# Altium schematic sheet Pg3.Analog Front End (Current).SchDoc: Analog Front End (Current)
size 431 x 279 mm; Date: Not shown in title block; ApprovedBy: Not shown in title block; CheckedBy: Not shown in title block; Author: Not shown in title block; CompanyName: Not shown in title block; Engineer: Not shown in title block; Organization: Not shown in title block; Address1: Not shown in title block; Address2: Not shown in title block; Address3: Not shown in title block; Address4: Not shown in title block; DocumentNumber: 3; Revision: Use project parameter SCH_Rev; SheetNumber: 3; SheetTotal: 8; PageSetup: Record=PageOptions|CenterHorizontal=True|CenterVertical=True|PrintScale=1.00|XCorrection=1.00|YCorrection=1.00|PrintKind=0|BorderSize=5000000|LeftOffset=0|BottomOffset=0|Orientation=2|PaperLength=1000|PaperWidth=1000|Scale=100|PaperSource=15|PrintQuality=600|MediaType=1|DitherType=10|PaperKind=Letter|PrintScaleMode=1
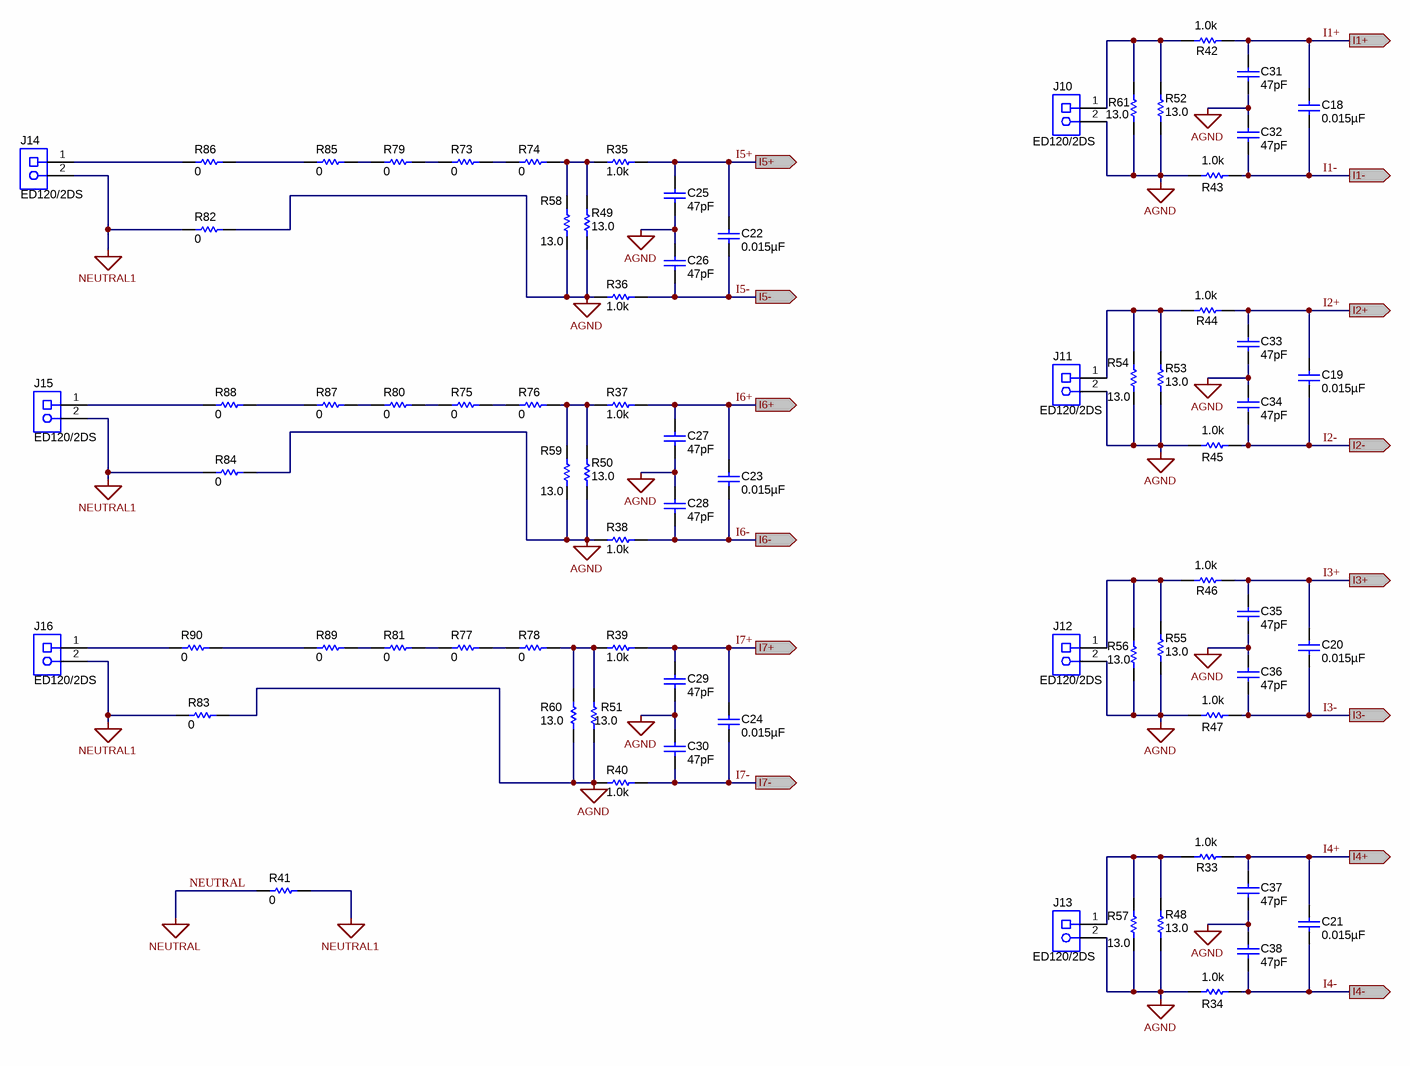
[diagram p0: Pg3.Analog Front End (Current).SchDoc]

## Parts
C18  ValueDisplayed: 0.015µF  [0805_HV]  (hidden comment: 08055C153KAT2A)
C19  ValueDisplayed: 0.015µF  [0805_HV]  (hidden comment: 08055C153KAT2A)
C20  ValueDisplayed: 0.015µF  [0805_HV]  (hidden comment: 08055C153KAT2A)
C21  ValueDisplayed: 0.015µF  [0805_HV]  (hidden comment: 08055C153KAT2A)
C22  ValueDisplayed: 0.015µF  [0805_HV]  (hidden comment: 08055C153KAT2A)
C23  ValueDisplayed: 0.015µF  [0805_HV]  (hidden comment: 08055C153KAT2A)
C24  ValueDisplayed: 0.015µF  [0805_HV]  (hidden comment: 08055C153KAT2A)
C25  ValueDisplayed: 47pF  [0805_HV]  (hidden comment: GRM21A5C2E470JW01D)
C26  ValueDisplayed: 47pF  [0805_HV]  (hidden comment: GRM21A5C2E470JW01D)
C27  ValueDisplayed: 47pF  [0805_HV]  (hidden comment: GRM21A5C2E470JW01D)
C28  ValueDisplayed: 47pF  [0805_HV]  (hidden comment: GRM21A5C2E470JW01D)
C29  ValueDisplayed: 47pF  [0805_HV]  (hidden comment: GRM21A5C2E470JW01D)
C30  ValueDisplayed: 47pF  [0805_HV]  (hidden comment: GRM21A5C2E470JW01D)
C31  ValueDisplayed: 47pF  [0805_HV]  (hidden comment: GRM21A5C2E470JW01D)
C32  ValueDisplayed: 47pF  [0805_HV]  (hidden comment: GRM21A5C2E470JW01D)
C33  ValueDisplayed: 47pF  [0805_HV]  (hidden comment: GRM21A5C2E470JW01D)
C34  ValueDisplayed: 47pF  [0805_HV]  (hidden comment: GRM21A5C2E470JW01D)
C35  ValueDisplayed: 47pF  [0805_HV]  (hidden comment: GRM21A5C2E470JW01D)
C36  ValueDisplayed: 47pF  [0805_HV]  (hidden comment: GRM21A5C2E470JW01D)
C37  ValueDisplayed: 47pF  [0805_HV]  (hidden comment: GRM21A5C2E470JW01D)
C38  ValueDisplayed: 47pF  [0805_HV]  (hidden comment: GRM21A5C2E470JW01D)
J10  ED120/2DS  [CONN_ED120-2DS]
J11  ED120/2DS  [CONN_ED120-2DS]
J12  ED120/2DS  [CONN_ED120-2DS]
J13  ED120/2DS  [CONN_ED120-2DS]
J14  ED120/2DS  [CONN_ED120-2DS]
J15  ED120/2DS  [CONN_ED120-2DS]
J16  ED120/2DS  [CONN_ED120-2DS]
R33  value 1.0k  [0603]  (hidden comment: CRCW06031K00JNEA)
R34  value 1.0k  [0603]  (hidden comment: CRCW06031K00JNEA)
R35  value 1.0k  [0603]  (hidden comment: CRCW06031K00JNEA)
R36  value 1.0k  [0603]  (hidden comment: CRCW06031K00JNEA)
R37  value 1.0k  [0603]  (hidden comment: CRCW06031K00JNEA)
R38  value 1.0k  [0603]  (hidden comment: CRCW06031K00JNEA)
R39  value 1.0k  [0603]  (hidden comment: CRCW06031K00JNEA)
R40  value 1.0k  [0603]  (hidden comment: CRCW06031K00JNEA)
R41  value 0  [0805_HV]  (hidden comment: CRCW08050000Z0EA)
R42  value 1.0k  [0603]  (hidden comment: CRCW06031K00JNEA)
R43  value 1.0k  [0603]  (hidden comment: CRCW06031K00JNEA)
R44  value 1.0k  [0603]  (hidden comment: CRCW06031K00JNEA)
R45  value 1.0k  [0603]  (hidden comment: CRCW06031K00JNEA)
R46  value 1.0k  [0603]  (hidden comment: CRCW06031K00JNEA)
R47  value 1.0k  [0603]  (hidden comment: CRCW06031K00JNEA)
R48  value 13.0  [0805_HV]  (hidden comment: CRCW080513R0FKEA)
R49  value 13.0  [0805_HV]  (hidden comment: CRCW080513R0FKEA)
R50  value 13.0  [0805_HV]  (hidden comment: CRCW080513R0FKEA)
R51  value 13.0  [0805_HV]  (hidden comment: CRCW080513R0FKEA)
R52  value 13.0  [0805_HV]  (hidden comment: CRCW080513R0FKEA)
R53  value 13.0  [0805_HV]  (hidden comment: CRCW080513R0FKEA)
R54  value 13.0  [0805_HV]  (hidden comment: CRCW080513R0FKEA)
R55  value 13.0  [0805_HV]  (hidden comment: CRCW080513R0FKEA)
R56  value 13.0  [0805_HV]  (hidden comment: CRCW080513R0FKEA)
R57  value 13.0  [0805_HV]  (hidden comment: CRCW080513R0FKEA)
R58  value 13.0  [0805_HV]  (hidden comment: CRCW080513R0FKEA)
R59  value 13.0  [0805_HV]  (hidden comment: CRCW080513R0FKEA)
R60  value 13.0  [0805_HV]  (hidden comment: CRCW080513R0FKEA)
R61  value 13.0  [0805_HV]  (hidden comment: CRCW080513R0FKEA)
R73  value 0  [0805_HV]  (hidden comment: CRCW08050000Z0EA)
R74  value 0  [0805_HV]  (hidden comment: CRCW08050000Z0EA)
R75  value 0  [0805_HV]  (hidden comment: CRCW08050000Z0EA)
R76  value 0  [0805_HV]  (hidden comment: CRCW08050000Z0EA)
R77  value 0  [0805_HV]  (hidden comment: CRCW08050000Z0EA)
R78  value 0  [0805_HV]  (hidden comment: CRCW08050000Z0EA)
R79  value 0  [0805_HV]  (hidden comment: CRCW08050000Z0EA)
R80  value 0  [0805_HV]  (hidden comment: CRCW08050000Z0EA)
R81  value 0  [0805_HV]  (hidden comment: CRCW08050000Z0EA)
R82  value 0  [0805_HV]  (hidden comment: CRCW08050000Z0EA)
R83  value 0  [0805_HV]  (hidden comment: CRCW08050000Z0EA)
R84  value 0  [0805_HV]  (hidden comment: CRCW08050000Z0EA)
R85  value 0  [0805_HV]  (hidden comment: CRCW08050000Z0EA)
R86  value 0  [0805_HV]  (hidden comment: CRCW08050000Z0EA)
R87  value 0  [0805_HV]  (hidden comment: CRCW08050000Z0EA)
R88  value 0  [0805_HV]  (hidden comment: CRCW08050000Z0EA)
R89  value 0  [0805_HV]  (hidden comment: CRCW08050000Z0EA)
R90  value 0  [0805_HV]  (hidden comment: CRCW08050000Z0EA)

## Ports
I1+ (out), I1- (out), I2+ (out), I2- (out), I3+ (out), I3- (out), I4+ (out), I4- (out), I5+ (out), I5- (out), I6+ (out), I6- (out), I7+ (out), I7- (out)

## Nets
AGND: C25.2 C26.1 C27.2 C28.1 C29.2 C30.1 C31.2 C32.1 C33.2 C34.1 C35.2 C36.1 C37.2 C38.1 J10.2 J11.2 J12.2 J13.2 R34.2 R36.2 R38.2 R40.2 R43.2 R45.2 R47.2 R48.1 R49.2 R50.2 R51.1 R52.1 R53.1 R54.1 R55.1 R56.1 R57.1 R58.1 R59.1 R60.2 R61.1 R82.2 R83.2 R84.2
NEUTRAL: R41.1
NEUTRAL1: J14.2 J15.2 J16.2 R41.2 R82.1 R83.1 R84.1
I1+: C18.1 C31.1 R42.1 ; port I1+
I1-: C18.2 C32.2 R43.1 ; port I1-
I2+: C19.1 C33.1 R44.1 ; port I2+
I2-: C19.2 C34.2 R45.1 ; port I2-
I3+: C20.1 C35.1 R46.1 ; port I3+
I3-: C20.2 C36.2 R47.1 ; port I3-
I4+: C21.1 C37.1 R33.1 ; port I4+
I4-: C21.2 C38.2 R34.1 ; port I4-
I5+: C22.1 C25.1 R35.1 ; port I5+
I5-: C22.2 C26.2 R36.1 ; port I5-
I6+: C23.1 C27.1 R37.1 ; port I6+
I6-: C23.2 C28.2 R38.1 ; port I6-
I7+: C24.1 C29.1 R39.1 ; port I7+
I7-: C24.2 C30.2 R40.1 ; port I7-
NetJ10_1: J10.1 R42.2 R52.2 R61.2
NetJ11_1: J11.1 R44.2 R53.2 R54.2
NetJ12_1: J12.1 R46.2 R55.2 R56.2
NetJ13_1: J13.1 R33.2 R48.2 R57.2
NetJ14_1: J14.1 R86.1
NetJ15_1: J15.1 R88.1
NetJ16_1: J16.1 R90.1
NetR35_2: R35.2 R49.1 R58.2 R74.2
NetR37_2: R37.2 R50.1 R59.2 R76.2
NetR39_2: R39.2 R51.2 R60.1 R78.2
NetR73_1: R73.1 R79.2
NetR73_2: R73.2 R74.1
NetR75_1: R75.1 R80.2
NetR75_2: R75.2 R76.1
NetR77_1: R77.1 R81.2
NetR77_2: R77.2 R78.1
NetR79_1: R79.1 R85.2
NetR80_1: R80.1 R87.2
NetR81_1: R81.1 R89.2
NetR85_1: R85.1 R86.2
NetR87_1: R87.1 R88.2
NetR89_1: R89.1 R90.2

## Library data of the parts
C18-C24 = 08055C153KAT2A: CAP, CERM, 0.015uF, 50V, +/-10%, X7R, 0805; Manufacturer: AVX; Polarized: N; CompType: Capacitor; U/M: EA; Cap_F: 0.000000015; Tolerance_%: 10; ESR_Ohm: 0.063; Value1: 0.063 ohm; VDC_V: 50; TaMin_C: -55; TaMax_C: 125; Cap_Case: 0805
C25-C38 = GRM21A5C2E470JW01D: CAP, CERM, 47pF, 500V, +/-5%, C0G/NP0, 0805; Manufacturer: MuRata; Polarized: N; CompType: Capacitor; U/M: EA; Cap_F: 0.000000000047; Tolerance_%: 5; Value1: Unknown; VDC_V: 250; Value2: 250V; TaMin_C: -55; TaMax_C: 125; Cap_Case: 0805
J10-J16 = ED120/2DS: TERMINAL BLOCK 5.08MM VERT 2POS, TH; Manufacturer: On-Shore Technology; SymbolCreator: a0412235; U/M: EA
R33-R40 R42-R47 = RC0603JR-071KL: RES, 1.0k ohm, 5%, 0.1W, 0603; Manufacturer: Vishay-Dale; CompType: Resistor; Res_ohm: 1000; Value_Code: 1k00; Tolerance_%: 5; Power_W: 0.1; VDC_V: 50; TempCo: 100 ppm/C; EIA_Code: E24; U/M: EA
R41 R73-R90 = CRCW0805330KJNEA: RES, 0 ohm, 5%, 0.125W, 0805; Manufacturer: Vishay-Dale; CompType: Resistor; Tolerance_%: 5; Power_W: 0.125; VDC_V: 150; TempCo: 200 ppm/C; EIA_Code: E24; U/M: EA
R48-R61 = CRCW080513R0FKEA: RES, 13.0 ohm, 1%, 0.125W, 0805; Manufacturer: Vishay-Dale; CompType: Resistor; Res_ohm: 13; Value_Code: 13R0; Tolerance_%: 1; Power_W: 0.125; VDC_V: 150; TempCo: 100 ppm/C; EIA_Code: E96; U/M: EA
